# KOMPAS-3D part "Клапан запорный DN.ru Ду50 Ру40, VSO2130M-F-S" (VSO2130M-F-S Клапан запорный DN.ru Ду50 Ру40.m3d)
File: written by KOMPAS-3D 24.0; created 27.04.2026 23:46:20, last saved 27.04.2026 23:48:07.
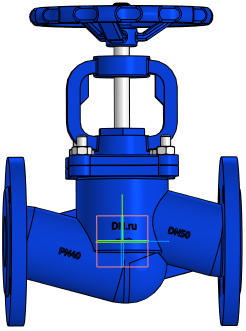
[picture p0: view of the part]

Document properties: Автор: DN.ru; Полное имя файла: C:\Работа\ГОТОВЫЕ ИСХОДНИКИ\VSO2130M-F-S Клапан запорный сальниковый DN.ru Ду15-100 Ру40\DN50\VSO2130M-F-S Клапан запорный DN.ru Ду50 Ру40.m3d

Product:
- Part/product: Клапан запорный DN.ru Ду50 Ру40  | designation VSO2130M-F-S
    Масса: 15
    Раздел спецификации: Прочие изделия
    Примечание: D090-01984

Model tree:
1. Операция без истории:1

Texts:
  VSO2130M-F-S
